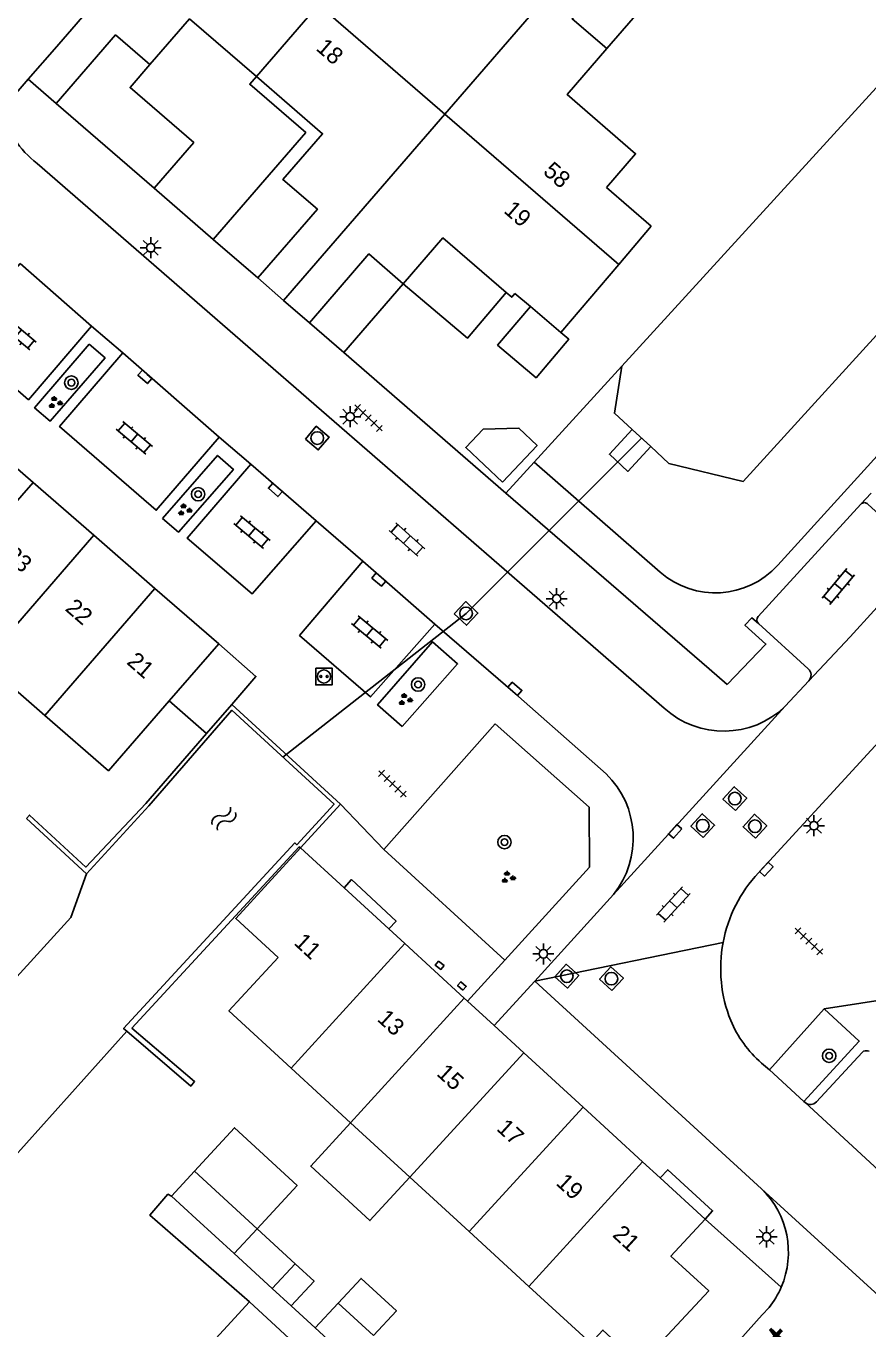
# Model space of a CAD drawing. Extents: x 128000 to 131008, y 398996 to 402500.
# Drawn here: x 129038.2 to 129088.3, y 399525.5 to 399603 of the extents above; entities that cross this region are included whole.
import ezdxf

# ---------------------------------------------------------------- set-up
doc = ezdxf.new("R2010")
doc.units = 0
for name, color, linetype in [('gg-afsc-erfafscheiding', 7, 'Continuous'), ('gg-anno-huisnummerreeks BGT', 7, 'Continuous'), ('gg-anno-openbare ruimte label', 7, 'Continuous'), ('gg-bbg-gedigitaliseerde bebouwing', 7, 'Continuous'), ('gg-bbg-gedigitaliseerde bijgebouw', 7, 'Continuous'), ('gg-bbg-hoofdgebouw', 7, 'Continuous'), ('gg-bbg-luifel en loopbrug', 7, 'Continuous'), ('gg-bbg-tussenscheiding', 7, 'Continuous'), ('gg-knt-BGT kruinlijn', 7, 'Continuous'), ('gg-knt-verharding', 7, 'Continuous'), ('gg-knt-verharding nz', 7, 'Continuous'), ('gg-kntw-beschoeiing', 7, 'Continuous'), ('gg-kntw-kademuur', 7, 'Continuous'), ('gg-kwrk-duiker nz buis', 7, 'Continuous'), ('gg-kwrk-uitstroombak niveau min 01', 7, 'Continuous'), ('gt-grn-vlakafsluiter', 7, 'Continuous'), ('gt-grn-weggrens', 7, 'Continuous'), ('gt-symb-boom', 7, 'Continuous'), ('gt-symb-groenvak', 7, 'Continuous'), ('gt-symb-klinker verharding', 7, 'Continuous'), ('gt-symb-kolk', 7, 'Continuous'), ('gt-symb-kolk center center', 7, 'Continuous'), ('gt-symb-laadpunt elektrisch vervoer', 7, 'Continuous'), ('gt-symb-lichtmast', 7, 'Continuous'), ('gt-symb-rioolschacht', 7, 'Continuous'), ('gt-symb-tegel verharding', 7, 'Continuous'), ('gt-symb-watersymbool', 7, 'Continuous')]:
    doc.layers.add(name, color=color, linetype=linetype)

# ---------------------------------------------------------------- blocks, each defined once
blk = doc.blocks.new('gt0-LMAST')
at = {"layer": 'gt-symb-lichtmast'}
for p, q in [((-0.182, 0.173), (-0.447, 0.438)), ((-0.005, 0.246), (-0.005, 0.621)), ((0.172, 0.173), (0.437, 0.438)), ((-0.255, -0.004), (-0.63, -0.004)), ((-0.182, -0.181), (-0.447, -0.446)), ((-0.005, -0.254), (-0.005, -0.629)), ((0.437, -0.446), (0.172, -0.181)), ((0.245, -0.004), (0.62, -0.004))]:
    blk.add_line(p, q, dxfattribs=at)
blk.add_circle((-0.005, -0.004), 0.25, dxfattribs=at)
blk = doc.blocks.new('gt0-RS')
at = {"layer": 'gt-symb-rioolschacht'}
blk.add_lwpolyline([(-0.5, -0.5), (0.5, -0.5), (0.5, 0.5), (-0.5, 0.5)], close=True, dxfattribs=at)
blk.add_circle((0, 0), 0.375, dxfattribs=at)
blk = doc.blocks.new('gt0-TEG1')
at = {"layer": 'gt-symb-tegel verharding'}
for p, q in [((-1.125, 0), (1.125, 0)), ((-0.9, -0.25), (-0.9, 0.25)), ((-0.45, -0.25), (-0.45, 0.25)), ((0, -0.25), (0, 0.25)), ((0.45, -0.25), (0.45, 0.25)), ((0.9, -0.25), (0.9, 0.25))]:
    blk.add_line(p, q, dxfattribs=at)
blk = doc.blocks.new('gt0-KL1')
at = {"layer": 'gt-symb-klinker verharding'}
for p, q in [((-1.15, 0.3), (1.15, 0.3)), ((-1, -0.3), (-1, 0.3)), ((-0.5, 0.3), (-0.5, 0.45)), ((0, -0.3), (0, 0.3)), ((0.5, 0.3), (0.5, 0.45)), ((1, -0.3), (1, 0.3)), ((-1.15, -0.3), (1.15, -0.3)), ((-0.5, -0.45), (-0.5, -0.3)), ((0.5, -0.45), (0.5, -0.3))]:
    blk.add_line(p, q, dxfattribs=at)
blk = doc.blocks.new('gt0-GRVAK')
at = {"layer": 'gt-symb-groenvak'}
for p, q in [((-0.11, 0.189), (-0.228, 0.24)), ((-0.182, 0.153), (0.088, 0.153)), ((-0.091, 0.211), (-0.156, 0.322)), ((-0.047, 0.214), (-0.047, 0.393)), ((-0.004, 0.211), (0.061, 0.322)), ((0.015, 0.189), (0.133, 0.24)), ((0.262, -0.052), (0.197, 0.059)), ((0.305, -0.049), (0.305, 0.13)), ((0.349, -0.052), (0.414, 0.059)), ((-0.245, -0.228), (-0.363, -0.177)), ((-0.318, -0.264), (-0.047, -0.264)), ((-0.226, -0.206), (-0.291, -0.095)), ((-0.183, -0.203), (-0.183, -0.024)), ((-0.139, -0.206), (-0.074, -0.095)), ((-0.12, -0.228), (-0.002, -0.177)), ((0.243, -0.074), (0.125, -0.023)), ((0.17, -0.11), (0.441, -0.11)), ((0.368, -0.074), (0.486, -0.023))]:
    blk.add_line(p, q, dxfattribs=at)
blk = doc.blocks.new('gt0-BOOM')
at = {"layer": 'gt-symb-boom'}
for radius in [0.4, 0.2]:
    blk.add_circle((0, 0), radius, dxfattribs=at)
blk = doc.blocks.new('gt0-KOLK')
at = {"layer": 'gt-symb-kolk'}
blk.add_lwpolyline([(0, 0), (0.375, 0), (0.375, 0.4), (-0.375, 0.4), (-0.375, 0), (0, 0)], dxfattribs=at)
blk = doc.blocks.new('gt0-WA')
at = {"layer": 'gt-symb-watersymbool'}
for centre, start, end in [((-0.323, 0.022), 28.07249, 151.92751), ((0.427, 0.422), 208.07248, 331.92751), ((-0.323, -0.428), 28.07249, 151.92751), ((0.427, -0.028), 208.07248, 331.92751)]:
    blk.add_arc(centre, 0.425, start, end, dxfattribs=at)
blk = doc.blocks.new('gt0-KOLKCC')
at = {"layer": 'gt-symb-kolk center center'}
blk.add_lwpolyline([(-0.375, 0.2), (0.375, 0.2), (0.375, -0.2), (-0.375, -0.2)], close=True, dxfattribs=at)
blk = doc.blocks.new('gt0-LEV')
at = {"layer": 'gt-symb-laadpunt elektrisch vervoer'}
blk.add_lwpolyline([(-0.486, 0.501), (0.486, 0.501), (0.486, -0.499), (-0.486, -0.499)], close=True, dxfattribs=at)
for centre, radius in [((0, 0), 0.393), ((-0.186, 0), 0.0566), ((0.186, 0), 0.0566)]:
    blk.add_circle(centre, radius, dxfattribs=at)

msp = doc.modelspace()

# ---------------------------------------------------------------- linework, layer by layer
at = {"layer": 'gg-afsc-erfafscheiding'}
msp.add_line((129055.41, 399525.57), (129053.98, 399526.878), dxfattribs=at)
msp.add_lwpolyline([(129051.488, 399527.122), (129045.574, 399532.27), (129046.653, 399533.51), (129046.862, 399533.409)], dxfattribs=at)
at = {"layer": 'gg-bbg-gedigitaliseerde bebouwing'}
for p, q in [((129053.966, 399541.016), (129057.506, 399537.766)), ((129057.506, 399537.766), (129061.03, 399534.53)), ((129061.03, 399534.53), (129064.56, 399531.29)), ((129064.56, 399531.29), (129068.099, 399528.039)), ((129068.099, 399528.039), (129071.78, 399524.66)), ((129051.488, 399527.122), (129048.101, 399523.419)), ((129058.85, 399520.36), (129051.488, 399527.122))]:
    msp.add_line(p, q, dxfattribs=at)
for points in [[(129054.529, 399554.099), (129050.679, 399549.901), (129053.194, 399547.594)], [(129053.194, 399547.594), (129050.27, 399544.41), (129053.966, 399541.016)]]:
    msp.add_lwpolyline(points, dxfattribs=at)
at = {"layer": 'gg-bbg-gedigitaliseerde bijgebouw'}
for p, q in [((129046.862, 399533.409), (129048.232, 399534.889)), ((129048.232, 399534.889), (129051.957, 399531.457)), ((129048.33, 399532.05), (129046.862, 399533.409)), ((129050.58, 399529.99), (129048.33, 399532.05)), ((129051.957, 399531.457), (129054.22, 399529.38)), ((129052.84, 399527.92), (129050.58, 399529.99)), ((129054.22, 399529.38), (129052.84, 399527.92)), ((129056.77, 399527.04), (129055.41, 399525.57)), ((129058.875, 399525.108), (129056.77, 399527.04)), ((129055.41, 399525.57), (129057.66, 399523.5))]:
    msp.add_line(p, q, dxfattribs=at)
msp.add_lwpolyline([(129066.529, 399575.845), (129068.595, 399578.021), (129067.507, 399579.053), (129065.386, 399578.999), (129064.354, 399577.911), (129066.529, 399575.845)], dxfattribs=at)
at = {"layer": 'gg-bbg-hoofdgebouw'}
for p, q in [((129039.899, 399601.587), (129047.928, 399610.847)), ((129038.341, 399599.79), (129039.899, 399601.587)), ((129040.01, 399598.35), (129038.341, 399599.79)), ((129072.713, 399593.349), (129075.378, 399591.051)), ((129075.378, 399591.051), (129073.443, 399588.777)), ((129073.443, 399588.777), (129070.005, 399584.736)), ((129051.99, 399587.98), (129053.527, 399586.649)), ((129068.19, 399586.28), (129067.276, 399587.057)), ((129053.527, 399586.649), (129055.06, 399585.32)), ((129070.005, 399584.736), (129068.19, 399586.28)), ((129035.01, 399578.97), (129038.633, 399575.823)), ((129038.633, 399575.823), (129042.246, 399572.687)), ((129042.246, 399572.687), (129045.88, 399569.53)), ((129045.88, 399569.53), (129049.67, 399566.24)), ((129046.719, 399562.843), (129049.67, 399566.24)), ((129035.699, 399565.129), (129039.326, 399561.977)), ((129054.529, 399554.099), (129057.118, 399551.724)), ((129057.118, 399551.724), (129059.782, 399549.282)), ((129059.782, 399549.282), (129060.73, 399548.412)), ((129060.73, 399548.412), (129064.266, 399545.168)), ((129064.266, 399545.168), (129064.458, 399544.992)), ((129064.458, 399544.992), (129066.04, 399543.541)), ((129066.04, 399543.541), (129067.798, 399541.929)), ((129067.798, 399541.929), (129071.334, 399538.686)), ((129071.334, 399538.686), (129074.865, 399535.447)), ((129074.865, 399535.447), (129075.913, 399534.486)), ((129075.913, 399534.486), (129078.58, 399532.04))]:
    msp.add_line(p, q, dxfattribs=at)
for points in [[(129074.22, 399607.46), (129070.68, 399603.38), (129072.73, 399601.61)], [(129045.58, 399600.66), (129047.94, 399603.38), (129051.905, 399599.953)], [(129040.01, 399598.35), (129043.54, 399602.43), (129045.58, 399600.66)], [(129072.73, 399601.61), (129070.37, 399598.89), (129074.45, 399595.36), (129072.713, 399593.349)], [(129051.905, 399599.953), (129055.841, 399596.55), (129053.48, 399593.83), (129055.53, 399592.06), (129051.99, 399587.98)], [(129066.755, 399587.111), (129062.99, 399590.36), (129060.64, 399587.64)], [(129060.64, 399587.64), (129058.6, 399589.41), (129055.06, 399585.32)], [(129067.276, 399587.057), (129067.08, 399586.83), (129066.755, 399587.111)], [(129039.326, 399561.977), (129043.11, 399558.69), (129046.719, 399562.843)], [(129078.58, 399532.04), (129076.55, 399529.83), (129078.79, 399527.781), (129074.71, 399523.39), (129072.501, 399525.44), (129071.78, 399524.66)]]:
    msp.add_lwpolyline(points, dxfattribs=at)
at = {"layer": 'gg-bbg-luifel en loopbrug'}
for p, q in [((129040.01, 399598.35), (129045.835, 399593.308)), ((129049.346, 399590.269), (129051.99, 399587.98)), ((129060.64, 399587.64), (129057.1, 399583.55)), ((129055.06, 399585.32), (129057.1, 399583.55)), ((129046.719, 399562.843), (129048.946, 399560.908)), ((129050.44, 399562.63), (129048.946, 399560.908)), ((129053.98, 399526.878), (129052.84, 399527.92))]:
    msp.add_line(p, q, dxfattribs=at)
for points in [[(129074.22, 399607.46), (129076.263, 399605.693), (129072.73, 399601.61)], [(129045.58, 399600.66), (129044.403, 399599.298), (129048.186, 399596.029), (129045.835, 399593.308)], [(129051.905, 399599.953), (129051.512, 399599.499), (129054.842, 399596.618), (129049.346, 399590.269)], [(129060.64, 399587.64), (129064.448, 399584.4), (129066.755, 399587.111)], [(129068.19, 399586.28), (129066.246, 399583.994), (129068.531, 399582.05), (129070.475, 399584.336), (129070.005, 399584.736)], [(129050.44, 399562.63), (129051.88, 399564.29), (129049.67, 399566.24)], [(129051.957, 399531.457), (129054.329, 399534.031), (129050.604, 399537.463), (129048.232, 399534.889)], [(129057.506, 399537.766), (129055.134, 399535.192), (129058.653, 399531.95), (129061.03, 399534.53)], [(129053.98, 399526.878), (129055.337, 399528.351), (129054.22, 399529.38)], [(129058.875, 399525.108), (129060.23, 399526.579), (129058.129, 399528.515), (129056.77, 399527.04)]]:
    msp.add_lwpolyline(points, dxfattribs=at)
at = {"layer": 'gg-bbg-tussenscheiding'}
for p, q in [((129063.104, 399597.72), (129072.682, 399608.792)), ((129051.905, 399599.953), (129055.595, 399604.215)), ((129055.595, 399604.215), (129063.104, 399597.72)), ((129053.527, 399586.649), (129063.104, 399597.72)), ((129063.104, 399597.72), (129073.443, 399588.777)), ((129032.065, 399568.286), (129038.633, 399575.823)), ((129035.699, 399565.129), (129042.246, 399572.687)), ((129039.326, 399561.977), (129045.88, 399569.53)), ((129053.966, 399541.016), (129060.73, 399548.412)), ((129057.506, 399537.766), (129064.266, 399545.168)), ((129061.03, 399534.53), (129067.798, 399541.929)), ((129064.56, 399531.29), (129071.334, 399538.686)), ((129068.099, 399528.039), (129074.865, 399535.447)), ((129050.58, 399529.99), (129051.957, 399531.457))]:
    msp.add_line(p, q, dxfattribs=at)
at = {"layer": 'gg-knt-BGT kruinlijn'}
msp.add_line((129075.91, 399570.49), (129068.424, 399577.028), dxfattribs=at)
msp.add_lwpolyline([(129082.899, 399570.899), (129112.27, 399603.23), (129113.85, 399604.47), (129115.82, 399605.67)], dxfattribs=at)
msp.add_arc((129079.195, 399574.268), 5.007, 228.99333, 317.70499, dxfattribs=at)
at = {"layer": 'gg-knt-verharding'}
for p, q in [((129121.466, 399595.946), (129081.749, 399552.619)), ((129076.147, 399562.409), (129038.869, 399594.782)), ((129045.835, 399593.308), (129049.346, 399590.269)), ((129042.101, 399585.12), (129043.969, 399583.521)), ((129057.1, 399583.55), (129066.74, 399575.184)), ((129049.694, 399578.516), (129051.581, 399576.911)), ((129066.74, 399575.184), (129078.822, 399564.747)), ((129088.448, 399575.194), (129087.836, 399574.538)), ((129081.737, 399567.863), (129087.836, 399574.538)), ((129088.256, 399574.534), (129091.219, 399571.827)), ((129055.462, 399573.547), (129058.227, 399571.144)), ((129084.71, 399564.753), (129081.745, 399567.435)), ((129078.822, 399564.747), (129079.879, 399563.82)), ((129083.341, 399562.517), (129084.746, 399564.037)), ((129059.481, 399554.015), (129066.094, 399561.475)), ((129071.689, 399559.395), (129072.695, 399558.508)), ((129059.481, 399554.015), (129066.669, 399547.424)), ((129073.131, 399551.329), (129068.46, 399546.18)), ((129066.669, 399547.424), (129064.458, 399544.992)), ((129068.46, 399546.18), (129081.937, 399533.842)), ((129082.406, 399540.91), (129085.646, 399544.54)), ((129087.904, 399541.946), (129085.198, 399539.01)), ((129082.406, 399540.91), (129081.933, 399541.31)), ((129084.444, 399539.029), (129082.406, 399540.91)), ((129084.518, 399538.961), (129084.444, 399539.029)), ((129082.376, 399526.775), (129081.973, 399526.336)), ((129076.599, 399520.395), (129081.973, 399526.336))]:
    msp.add_line(p, q, dxfattribs=at)
for points in [[(129037.867, 399588.832), (129034.108, 399584.441), (129038.352, 399580.738), (129042.101, 399585.12)], [(129041.977, 399584.039), (129042.914, 399583.231), (129039.64, 399579.46), (129038.719, 399580.262), (129041.977, 399584.039)], [(129043.969, 399583.521), (129040.206, 399579.15), (129045.959, 399574.167), (129049.694, 399578.516)], [(129046.326, 399573.674), (129049.599, 399577.43), (129050.539, 399576.604), (129047.271, 399572.863), (129046.326, 399573.674)], [(129051.581, 399576.911), (129047.796, 399572.506), (129051.661, 399569.209), (129055.462, 399573.547)], [(129058.227, 399571.144), (129054.471, 399566.735), (129058.686, 399563.074), (129062.514, 399567.406)], [(129062.514, 399567.406), (129067.141, 399563.403), (129071.689, 399559.395)], [(129079.879, 399563.82), (129082.188, 399566.212), (129080.948, 399567.333), (129081.361, 399567.781), (129081.745, 399567.435)], [(129060.575, 399561.32), (129059.111, 399562.601), (129062.374, 399566.348), (129063.864, 399565.035), (129060.575, 399561.32)], [(129066.094, 399561.475), (129071.685, 399556.523), (129071.702, 399552.959), (129066.669, 399547.424)], [(129059.782, 399549.282), (129060.214, 399549.745), (129057.567, 399552.214), (129057.118, 399551.724)], [(129063.074, 399547.112), (129062.734, 399547.365), (129062.531, 399547.133), (129062.871, 399546.88), (129063.074, 399547.112)], [(129064.176, 399545.638), (129064.376, 399545.867), (129064.061, 399546.146), (129063.861, 399545.917), (129064.176, 399545.638)], [(129085.646, 399544.54), (129087.741, 399542.62), (129084.444, 399539.029)], [(129078.58, 399532.04), (129079.019, 399532.531), (129076.353, 399534.965), (129075.913, 399534.486)]]:
    msp.add_lwpolyline(points, dxfattribs=at)
for centre, radius, start, end in [((129042.288, 399599.226), 5.607, 192.39772, 232.42329), ((129088.044, 399574.326), 0.297, 44.4465, 134.46218), ((129081.961, 399567.653), 0.307, 136.83519, 225.30646), ((129084.359, 399564.376), 0.515, 318.76981, 46.98693), ((129079.686, 399566.305), 5.264, 227.74625, 313.97392), ((129068.951, 399554.678), 5.356, 321.30283, 45.64808), ((129087.808, 399546.939), 8.305, 136.85349, 169.36614), ((129087.81, 399546.938), 8.307, 169.36056, 201.86938), ((129086.44, 399546.498), 6.873, 202.71628, 229.01515), ((129088.167, 399541.673), 0.379, 63.80961, 133.90293), ((129084.833, 399539.334), 0.488, 229.79379, 318.44929), ((129078.252, 399530.066), 5.276, 336.81472, 45.6997), ((129078.257, 399530.062), 5.27, 321.40699, 336.83221)]:
    msp.add_arc(centre, radius, start, end, dxfattribs=at)
at = {"layer": 'gg-knt-verharding nz'}
for p, q in [((129037.867, 399588.832), (129042.101, 399585.12)), ((129043.969, 399583.521), (129049.694, 399578.516)), ((129051.581, 399576.911), (129055.462, 399573.547)), ((129091.922, 399571.855), (129087.202, 399566.656)), ((129058.227, 399571.144), (129062.514, 399567.406)), ((129087.202, 399566.656), (129084.746, 399564.037))]:
    msp.add_line(p, q, dxfattribs=at)
msp.add_lwpolyline([(129084.518, 399538.961), (129098.136, 399526.397), (129115.735, 399510.323), (129119.29, 399507.158)], dxfattribs=at)
at = {"layer": 'gg-kntw-beschoeiing'}
msp.add_line((129073.63, 399582.73), (129104.68, 399616.74), dxfattribs=at)
for points in [[(129104.68, 399616.74), (129108.09, 399616.92), (129111.88, 399613.54), (129111.93, 399610.03), (129080.83, 399575.89), (129076.43, 399576.96), (129075.352, 399577.952)], [(129074.242, 399578.972), (129073.19, 399579.94), (129073.63, 399582.73)], [(129041.8, 399552.559), (129040.875, 399549.962), (129025.23, 399532.784), (129015.23, 399521.935)], [(129022.333, 399514.972), (129034.28, 399528.254), (129034.165, 399532.102), (129036.526, 399534.639), (129044.201, 399543.199)]]:
    msp.add_lwpolyline(points, dxfattribs=at)
at = {"layer": 'gg-kntw-kademuur'}
for p, q in [((129050.44, 399562.63), (129056.91, 399556.7)), ((129056.91, 399556.7), (129054.529, 399554.099)), ((129038.233, 399555.839), (129041.8, 399552.559))]:
    msp.add_line(p, q, dxfattribs=at)
for points in [[(129041.8, 399552.559), (129045.52, 399556.6), (129050.45, 399562.28), (129056.52, 399556.71), (129054.316, 399554.293), (129054.2, 399554.4), (129044.01, 399543.362), (129044.201, 399543.199)], [(129048.946, 399560.908), (129045.34, 399556.75), (129041.779, 399552.961), (129038.424, 399556.047), (129038.233, 399555.839)], [(129054.529, 399554.099), (129054.459, 399554.163), (129044.513, 399543.392), (129048.231, 399540.21), (129048.004, 399539.944), (129044.201, 399543.199)]]:
    msp.add_lwpolyline(points, dxfattribs=at)
at = {"layer": 'gg-kwrk-duiker nz buis'}
msp.add_lwpolyline([(129053.485, 399559.495), (129064.371, 399568.038), (129074.797, 399578.462)], dxfattribs=at)
at = {"layer": 'gg-kwrk-uitstroombak niveau min 01'}
msp.add_line((129075.352, 399577.952), (129074.242, 399578.972), dxfattribs=at)
msp.add_lwpolyline([(129074.242, 399578.972), (129072.89, 399577.501), (129073.99, 399576.48), (129075.352, 399577.952)], dxfattribs=at)
at = {"layer": 'gt-grn-vlakafsluiter'}
for p, q in [((129073.63, 399582.73), (129068.424, 399577.028)), ((129068.424, 399577.028), (129066.74, 399575.184))]:
    msp.add_line(p, q, dxfattribs=at)
at = {"layer": 'gt-grn-weggrens'}
for p, q in [((129038.341, 399599.79), (129036.812, 399598.022)), ((129073.131, 399551.329), (129083.341, 399562.517)), ((129059.481, 399554.015), (129056.91, 399556.7)), ((129068.46, 399546.18), (129079.646, 399548.472)), ((129066.04, 399543.541), (129068.46, 399546.18)), ((129090.57, 399545.3), (129085.646, 399544.54)), ((129081.937, 399533.842), (129093.257, 399523.479)), ((129083.102, 399527.989), (129078.58, 399532.04))]:
    msp.add_line(p, q, dxfattribs=at)

# ---------------------------------------------------------------- block references
at = {"layer": 'gt-symb-boom'}
for p in [(129040.91, 399581.755), (129048.444, 399575.124), (129061.517, 399563.815), (129066.65, 399554.445), (129085.951, 399541.744)]:
    msp.add_blockref('gt0-BOOM', p, dxfattribs=at)
at = {"layer": 'gt-symb-groenvak'}
for p in [(129039.934, 399580.568), (129047.625, 399574.188), (129060.734, 399562.915), (129066.852, 399552.34)]:
    msp.add_blockref('gt0-GRVAK', p, dxfattribs=at)
at = {"layer": 'gt-symb-klinker verharding'}
for p, rotation in [((129037.749, 399584.676), -40.09168080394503), ((129044.653, 399578.471), -40.091680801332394), ((129051.645, 399572.878), -40.091680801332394), ((129060.857, 399572.43), -41.919064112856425), ((129086.494, 399569.634), 50.0697455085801), ((129058.637, 399566.935), -40.091680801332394), ((129076.687, 399550.743), 47.55289814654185)]:
    msp.add_blockref('gt0-KL1', p, dxfattribs=dict(at, rotation=rotation))
at = {"layer": 'gt-symb-kolk'}
for p, rotation in [((129045.41, 399582.251), 138.60919760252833), ((129053.167, 399575.534), 139.01346679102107), ((129059.319, 399570.2), 139.1750647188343), ((129067.141, 399563.403), -40.86240641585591), ((129082.069, 399552.97), -132.4471018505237)]:
    msp.add_blockref('gt0-KOLK', p, dxfattribs=dict(at, rotation=rotation))
at = {"layer": 'gt-symb-kolk center center', "rotation": -132.5168918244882}
msp.add_blockref('gt0-KOLKCC', (129076.799, 399555.087), dxfattribs=at)
at = {"layer": 'gt-symb-laadpunt elektrisch vervoer'}
msp.add_blockref('gt0-LEV', (129055.924, 399564.293), dxfattribs=at)
at = {"layer": 'gt-symb-lichtmast'}
for p in [(129045.631, 399589.777), (129057.487, 399579.735), (129069.759, 399568.92), (129085.053, 399555.424), (129068.973, 399547.806), (129082.239, 399530.986)]:
    msp.add_blockref('gt0-LMAST', p, dxfattribs=at)
at = {"layer": 'gt-symb-rioolschacht'}
for p, rotation in [((129055.525, 399578.46), -40.3339660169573), ((129064.371, 399568.038), -43.013893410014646), ((129080.345, 399557.033), 47.55289814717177), ((129078.439, 399555.42), 47.55289814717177), ((129081.539, 399555.391), 47.55289814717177), ((129070.358, 399546.475), -42.447101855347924), ((129073.011, 399546.328), 47.55289814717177)]:
    msp.add_blockref('gt0-RS', p, dxfattribs=dict(at, rotation=rotation))
at = {"layer": 'gt-symb-tegel verharding'}
for p, rotation in [((129058.565, 399579.659), -43.62257341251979), ((129059.991, 399557.915), -43.62257341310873), ((129084.745, 399548.551), -43.62257341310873)]:
    msp.add_blockref('gt0-TEG1', p, dxfattribs=dict(at, rotation=rotation))
at = {"layer": 'gt-symb-watersymbool', "rotation": 44.27067303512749}
msp.add_blockref('gt0-WA', (129049.939, 399555.813), dxfattribs=at)

# ---------------------------------------------------------------- texts
at = {"layer": 'gg-anno-huisnummerreeks BGT'}
for s, rotation, p in [('18', 319.1, (129055.397, 399601.562)), ('58', 319.1, (129068.893, 399594.219)), ('19', 319.2, (129066.555, 399591.906)), ('23', 319.1, (129036.889, 399571.377)), ('22', 319, (129040.487, 399568.256)), ('21', 319, (129044.144, 399565.08)), ('11', 317.5, (129054.084, 399548.401)), ('13', 317.5, (129059.031, 399543.864)), ('15', 317.5, (129062.565, 399540.622)), ('17', 317.5, (129066.129, 399537.354)), ('19', 317.5, (129069.659, 399534.116)), ('21', 317.5, (129073.016, 399531.037))]:
    msp.add_text(s, height=1, rotation=rotation, dxfattribs=at).set_placement(p)
at = {"layer": 'gg-anno-openbare ruimte label'}
msp.add_text('Benthuizenstraat', height=2.5, rotation=47.6, dxfattribs=at).set_placement((129067.574, 399505.755))

doc.saveas('drawing.dxf')
